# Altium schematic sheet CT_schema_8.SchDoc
size 368 x 243 mm
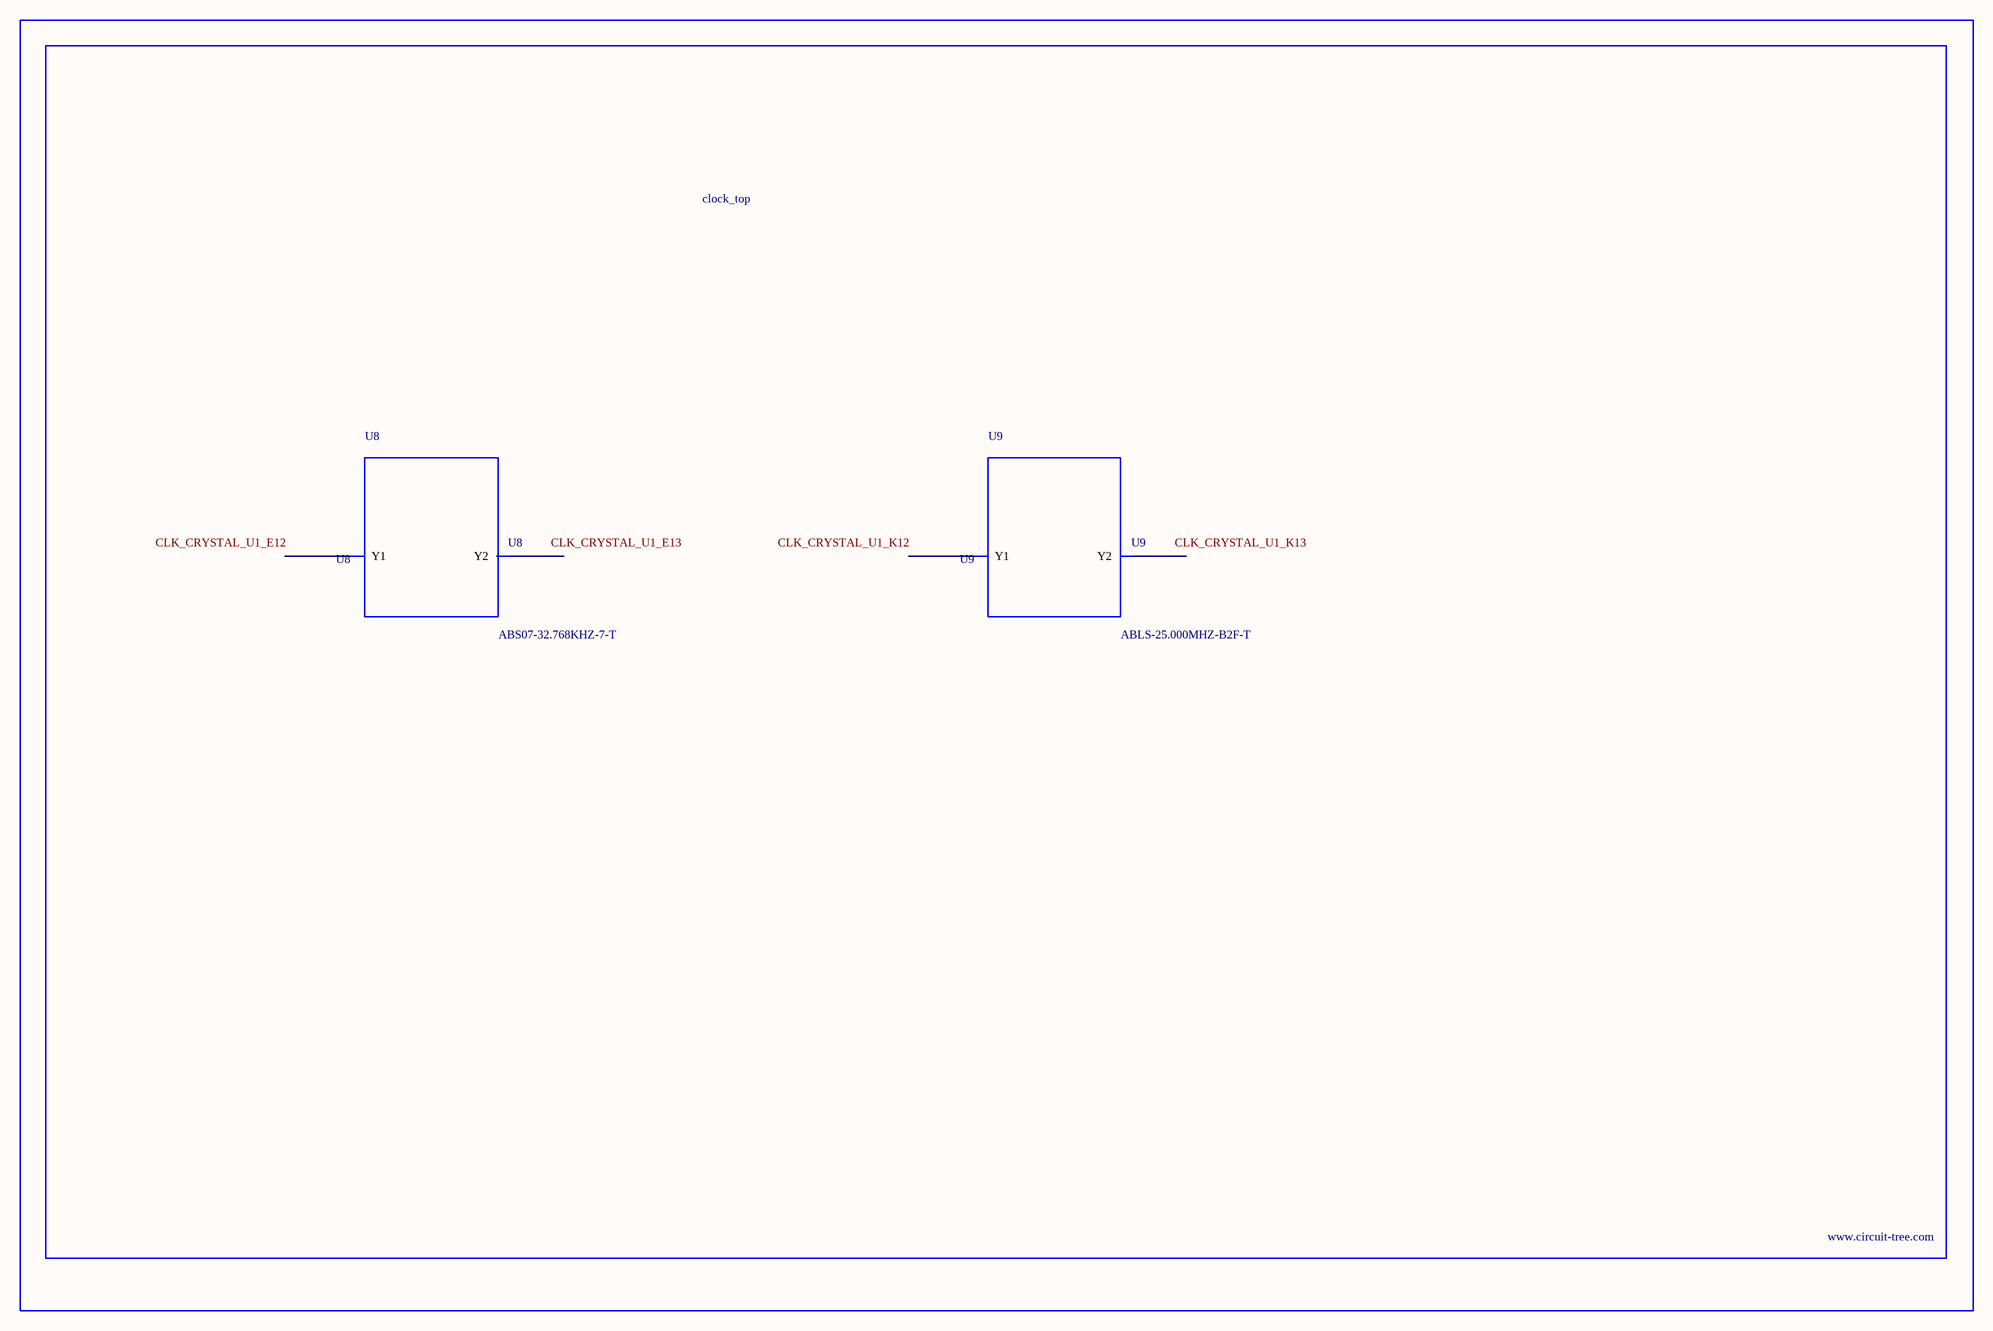
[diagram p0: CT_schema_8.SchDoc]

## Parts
BORDER7  (no value)
U8  ABS07-32.768KHZ-7-T  [ABS07-32.768KHZ-7-T]
U9  ABLS-25.000MHZ-B2F-T  [ABLS-25.000MHZ-B2F-T]

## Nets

Not connected (* = marked no-connect by the designer): U8 1(Y1) 2(Y2); U9 1(Y1) 2(Y2)

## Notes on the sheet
- Labels drawn without touching a wire or pin: CLK_CRYSTAL_U1_E12, CLK_CRYSTAL_U1_E13, CLK_CRYSTAL_U1_K12, CLK_CRYSTAL_U1_K13

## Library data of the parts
BORDER7 = BORDER_PAGE7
